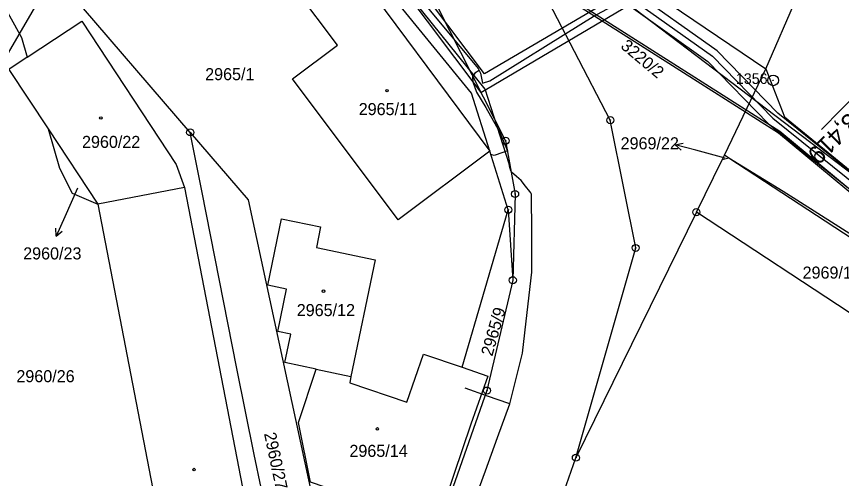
# Model space of a CAD drawing. Extents: x -620475 to -619963, y -1123010 to -1122510.
# Drawn here: x -620416.3 to -620299.9, y -1122766.6 to -1122701.4 of the extents above; entities that cross this region are included whole.
import ezdxf

# ---------------------------------------------------------------- set-up
doc = ezdxf.new("R2010")
doc.units = 0
for name, color, linetype in [('CETIN', 7, 'Continuous'), ('GasNet', 7, 'Continuous'), ('HranDP', 7, 'Continuous'), ('Hranice parcel', 7, 'Continuous'), ('Parcelní čísla', 7, 'Continuous'), ('Pop  PČ popisy', 7, 'Continuous'), ('Rámečky-tisk', 7, 'Continuous'), ('SSZT-DK', 7, 'Continuous'), ('VAS vodovod', 7, 'Continuous'), ('Vrstva 3', 7, 'Continuous'), ('Věcná břemena k části', 7, 'Continuous'), ('Značky bodu BP', 7, 'Continuous'), ('Značky budov', 7, 'Continuous'), ('ČD-T', 7, 'Continuous')]:
    doc.layers.add(name, color=color, linetype=linetype)

msp = doc.modelspace()

# ---------------------------------------------------------------- linework, layer by layer
at = {"layer": 'CETIN'}
msp.add_lwpolyline([(-620398.07, -1122646.12), (-620362.48, -1122674.84), (-620281.95, -1122736.09)], dxfattribs=at)
at = {"layer": 'GasNet'}
for points in [[(-620407.49, -1122656.88), (-620389.11, -1122672.47), (-620361.34, -1122696.38), (-620351.16, -1122708.72), (-620351, -1122709.02), (-620350.83, -1122709.39), (-620350.53, -1122710.79), (-620349.5, -1122710.44), (-620336.68, -1122702.48), (-620334.91, -1122701.4), (-620329.86, -1122698.6), (-620318.09, -1122706.99), (-620309.56, -1122715.75), (-620284.55, -1122735.89), (-620286.51, -1122738.72), (-620281.31, -1122742.82), (-620280.83, -1122743.2), (-620261.03, -1122754.43), (-620247.22, -1122761.95), (-620220.34, -1122775.27), (-620203.57, -1122783.96)], [(-620351, -1122709.02), (-620351.62, -1122709.36), (-620351.95, -1122709.89), (-620351.89, -1122710.61), (-620351.38, -1122712.06), (-620350.09, -1122714.22), (-620348.14, -1122717.64), (-620346.99, -1122720.36), (-620347.15, -1122720.39), (-620347.67, -1122720.57), (-620348.9, -1122720.99), (-620349.23, -1122720.89), (-620349.32, -1122720.93)]]:
    msp.add_lwpolyline(points, dxfattribs=at)
at = {"layer": 'HranDP'}
for points in [[(-620310.57, -1122708.76), (-620306.2, -1122698.65), (-620309.9, -1122688.62), (-620334.71, -1122668.63), (-620387.37, -1122633.88)], [(-620310.57, -1122708.76), (-620307.94, -1122715.53), (-620278.65, -1122739.48), (-620275.74, -1122741.01)]]:
    msp.add_lwpolyline(points, dxfattribs=at)
at = {"layer": 'Hranice parcel'}
for p, q in [((-620316.42, -1122720.94), (-620310.57, -1122708.76)), ((-620411.83, -1122717.24), (-620404.8, -1122727.88)), ((-620316.74, -1122721.6), (-620316.42, -1122720.94)), ((-620315.79, -1122721.36), (-620316.74, -1122721.6)), ((-620315.79, -1122721.36), (-620316.42, -1122720.94)), ((-620280.66, -1122744.45), (-620315.79, -1122721.36)), ((-620320.37, -1122729), (-620316.74, -1122721.6)), ((-620392.56, -1122725.51), (-620404.8, -1122727.88)), ((-620392.56, -1122725.51), (-620377.65, -1122802.63)), ((-620404.8, -1122727.88), (-620389.89, -1122805.11)), ((-620353.41, -1122750.9), (-620346.9, -1122728.66)), ((-620346.9, -1122728.66), (-620346.26, -1122738.61)), ((-620320.37, -1122729), (-620337.36, -1122763.66)), ((-620284.57, -1122752.56), (-620320.37, -1122729)), ((-620337.36, -1122763.66), (-620328.93, -1122734.05)), ((-620373.99, -1122751.17), (-620369.13, -1122752.19)), ((-620353.06, -1122808.63), (-620337.36, -1122763.66))]:
    msp.add_line(p, q, dxfattribs=at)
for points in [[(-620310.57, -1122708.76), (-620306.2, -1122698.65), (-620309.9, -1122688.62), (-620334.71, -1122668.63), (-620387.37, -1122633.88)], [(-620397.76, -1122645.76), (-620368.46, -1122669.58), (-620310.57, -1122708.76)], [(-620407.03, -1122656.36), (-620404.9, -1122658.18), (-620395.68, -1122667.41), (-620365.35, -1122691.52), (-620356.78, -1122700.2), (-620347.29, -1122718.92), (-620345.94, -1122726.44), (-620346.26, -1122738.61)], [(-620346.9, -1122728.66), (-620349.5, -1122720.4), (-620352.08, -1122712.18), (-620363.06, -1122698.75), (-620372.55, -1122689.97), (-620409.4, -1122659.07)], [(-620391.77, -1122717.74), (-620425.96, -1122678)], [(-620431.67, -1122684.53), (-620430.21, -1122685.42), (-620421.46, -1122693.76), (-620415.57, -1122704.35), (-620414.76, -1122707.13)], [(-620349.5, -1122720.4), (-620362.45, -1122730.09), (-620377.36, -1122710.19), (-620370.99, -1122705.44), (-620376.85, -1122697.59), (-620370.13, -1122692.59), (-620349.5, -1122720.4)], [(-620328.93, -1122734.05), (-620330.51, -1122726.08), (-620332.51, -1122716.01), (-620337.56, -1122706.31), (-620342.37, -1122697.07)], [(-620414.76, -1122707.13), (-620407.04, -1122702.06), (-620393.75, -1122722.26), (-620392.56, -1122725.51)], [(-620414.76, -1122707.13), (-620417.37, -1122708.84), (-620411.83, -1122717.24)], [(-620310.57, -1122708.76), (-620307.94, -1122715.53), (-620278.65, -1122739.48), (-620275.74, -1122741.01)], [(-620411.83, -1122717.24), (-620410.22, -1122722.77), (-620408.42, -1122726.33), (-620404.8, -1122727.88)], [(-620391.77, -1122717.74), (-620383.57, -1122727.26), (-620368.9, -1122795.38)], [(-620367.37, -1122802.49), (-620372.62, -1122803.29), (-620374.73, -1122803.66), (-620374.83, -1122803.1), (-620379.42, -1122780.06), (-620381.78, -1122767.9), (-620382.73, -1122763.21), (-620385.21, -1122751.08), (-620390.13, -1122725.98), (-620391.77, -1122717.74)], [(-620243.2, -1122764.91), (-620246.23, -1122763.17), (-620280.18, -1122743.84), (-620308.1, -1122726.09), (-620315.79, -1122721.36)], [(-620373.99, -1122751.17), (-620378.41, -1122750.24), (-620377.57, -1122746.24), (-620379.43, -1122745.85), (-620378.17, -1122739.85), (-620380.83, -1122739.29), (-620378.87, -1122729.94), (-620373.38, -1122731.07), (-620373.97, -1122734.01), (-620365.7, -1122735.74), (-620369.13, -1122752.19)], [(-620346.26, -1122738.61), (-620349.91, -1122754.18), (-620361.74, -1122787.84), (-620367.19, -1122803.33)], [(-620369.13, -1122752.19), (-620369.27, -1122753.08), (-620361.19, -1122755.84), (-620358.86, -1122749.03), (-620353.41, -1122750.9)], [(-620364.94, -1122785.63), (-620370.66, -1122783.71), (-620366.44, -1122771.24), (-620366.65, -1122771.17), (-620366.25, -1122770.01), (-620374.82, -1122767.12), (-620376.48, -1122758.71), (-620373.99, -1122751.17)], [(-620353.41, -1122750.9), (-620349.8, -1122752.13), (-620352.16, -1122758.92), (-620357, -1122773.13), (-620361.6, -1122786.76), (-620364.94, -1122785.63)]]:
    msp.add_lwpolyline(points, dxfattribs=at)
at = {"layer": 'Pop  PČ popisy'}
for p, q in [((-620323.34, -1122719.48), (-620322.24, -1122719.26)), ((-620320.44, -1122720.26), (-620323.34, -1122719.48)), ((-620323.34, -1122719.48), (-620322.5, -1122720.23)), ((-620316.31, -1122721.37), (-620320.44, -1122720.26)), ((-620407.69, -1122725.63), (-620409.46, -1122729.64)), ((-620409.46, -1122729.64), (-620410.68, -1122732.38)), ((-620410.68, -1122732.38), (-620410.73, -1122731.26)), ((-620410.68, -1122732.38), (-620409.82, -1122731.67))]:
    msp.add_line(p, q, dxfattribs=at)
at = {"layer": 'Rámečky-tisk'}
msp.add_lwpolyline([(-620471.94, -1122730.56), (-620441.66, -1122748.16), (-620351.12, -1122592.44)], dxfattribs=at)
at = {"layer": 'SSZT-DK'}
msp.add_lwpolyline([(-620400.12, -1122648.46), (-620392.31, -1122655.21), (-620359.04, -1122685.8), (-620308.77, -1122717.8), (-620291.41, -1122732.21), (-620277.2, -1122744.11), (-620257.61, -1122720.05), (-620250.25, -1122710.72), (-620233.29, -1122724.26), (-620218.7, -1122737.68), (-620210.44, -1122746.52), (-620193.32, -1122761.99), (-620178.35, -1122775.89), (-620171.18, -1122783.62), (-620164.84, -1122792.28), (-620156.69, -1122803.31), (-620146.31, -1122818.99), (-620117.64, -1122885.13), (-620110.3, -1122902.14)], dxfattribs=at)
at = {"layer": 'VAS vodovod'}
for points in [[(-620346.78, -1122722.2), (-620350.17, -1122711.62), (-620361.5, -1122697.5), (-620361.99, -1122696.76), (-620371.19, -1122688.51), (-620408.08, -1122657.56)], [(-620353.53, -1122774.89), (-620350.12, -1122765.53), (-620348.4, -1122760.79), (-620346.67, -1122756.05), (-620345.79, -1122752.48), (-620344.9, -1122748.91), (-620344.25, -1122743.18), (-620343.6, -1122737.45), (-620343.6, -1122731.96), (-620343.61, -1122726.46), (-620343.74, -1122726.27), (-620343.87, -1122726.08), (-620344.48, -1122725.31), (-620345.09, -1122724.54), (-620345.76, -1122723.95), (-620346.43, -1122723.35), (-620346.44, -1122723.33), (-620346.48, -1122723.26), (-620346.53, -1122723.17), (-620346.66, -1122722.69), (-620346.78, -1122722.2)], [(-620346.67, -1122756.05), (-620346.82, -1122756), (-620349.82, -1122754.95), (-620352.97, -1122753.85)]]:
    msp.add_lwpolyline(points, dxfattribs=at)
at = {"layer": 'Vrstva 3'}
msp.add_line((-620284.81, -1122699.02), (-620302.72, -1122717.32), dxfattribs=at)
at = {"layer": 'Věcná břemena k části'}
msp.add_lwpolyline([(-620408.15, -1122657.63), (-620389.78, -1122673.21), (-620362.07, -1122697.07), (-620350.79, -1122712.11), (-620329.91, -1122699.79), (-620318.75, -1122707.75), (-620310.23, -1122716.49), (-620285.9, -1122736.09), (-620287.87, -1122738.92), (-620280.66, -1122744.45), (-620246.32, -1122763.41), (-620202.66, -1122784.39), (-620201.79, -1122782.59), (-620245.45, -1122761.61), (-620279.7, -1122742.7), (-620285.15, -1122738.52), (-620283.23, -1122735.73), (-620308.89, -1122715.01), (-620317.45, -1122706.23), (-620329.81, -1122697.41), (-620350.27, -1122709.47), (-620360.61, -1122695.69), (-620388.48, -1122671.69), (-620406.83, -1122656.13)], dxfattribs=at)
at = {"layer": 'Značky bodu BP'}
for centre, radius in [((-620309.54, -1122710.4), 0.75), ((-620309.54, -1122710.4), 0.03), ((-620332.51, -1122716.01), 0.5), ((-620332.51, -1122716.01), 0.0303), ((-620391.77, -1122717.74), 0.5), ((-620391.77, -1122717.74), 0.0303), ((-620347.29, -1122718.92), 0.5), ((-620347.29, -1122718.92), 0.0303), ((-620345.94, -1122726.44), 0.5), ((-620345.94, -1122726.44), 0.0303), ((-620346.9, -1122728.66), 0.5), ((-620320.37, -1122729), 0.5), ((-620346.9, -1122728.66), 0.0303), ((-620320.37, -1122729), 0.0303), ((-620328.93, -1122734.05), 0.5), ((-620328.93, -1122734.05), 0.0303), ((-620346.26, -1122738.61), 0.5), ((-620346.26, -1122738.61), 0.0303), ((-620349.91, -1122754.18), 0.5), ((-620349.91, -1122754.18), 0.0303), ((-620337.36, -1122763.66), 0.5), ((-620337.36, -1122763.66), 0.0303)]:
    msp.add_circle(centre, radius, dxfattribs=at)
at = {"layer": 'Značky budov'}
for centre in [(-620364, -1122711.85), (-620404.38, -1122715.7), (-620372.97, -1122740.15), (-620365.36, -1122759.59), (-620391.23, -1122765.33)]:
    msp.add_circle(centre, 0.175, dxfattribs=at)
at = {"layer": 'ČD-T'}
msp.add_lwpolyline([(-620399.92, -1122648.23), (-620392.12, -1122654.98), (-620358.85, -1122685.56), (-620308.58, -1122717.56), (-620291.22, -1122731.97), (-620279.98, -1122741.46), (-620260.48, -1122717.47), (-620252.94, -1122708.19), (-620233.1, -1122724.03), (-620218.51, -1122737.45), (-620206.64, -1122747.53), (-620193.13, -1122761.76), (-620178.16, -1122775.66), (-620171, -1122783.39), (-620164.66, -1122792.05), (-620156.51, -1122803.08), (-620146.12, -1122818.76), (-620117.45, -1122884.9), (-620110.11, -1122901.9)], dxfattribs=at)

# ---------------------------------------------------------------- texts
at = {"layer": 'Parcelní čísla'}
for s, rotation, p in [('3220/2', 320, (-620331.16, -1122705.75)), ('2965/9', 74, (-620349.16, -1122749.42)), ('2960/27', 282, (-620381.37, -1122760.25))]:
    msp.add_text(s, height=1.7, rotation=rotation, dxfattribs=at).set_placement(p)
for s, p in [('2965/1', (-620389.66, -1122710.37)), ('2965/11', (-620368, -1122715.3)), ('2960/22', (-620407.03, -1122719.93)), ('2969/22', (-620331.05, -1122720.13)), ('2960/23', (-620415.33, -1122735.67)), ('2969/17', (-620305.38, -1122738.38)), ('2965/12', (-620376.74, -1122743.67)), ('2960/26', (-620416.29, -1122753)), ('2965/14', (-620369.31, -1122763.54))]:
    msp.add_text(s, height=1.7, dxfattribs=at).set_placement(p)
at = {"layer": 'Vrstva 3'}
msp.add_text('km 63,419', height=2.5, rotation=224.4932, dxfattribs=at).set_placement((-620293.75, -1122709.72))
at = {"layer": 'Značky bodu BP'}
msp.add_text('1356', height=1.5, dxfattribs=at).set_placement((-620314.79, -1122710.9))

doc.saveas('drawing.dxf')
